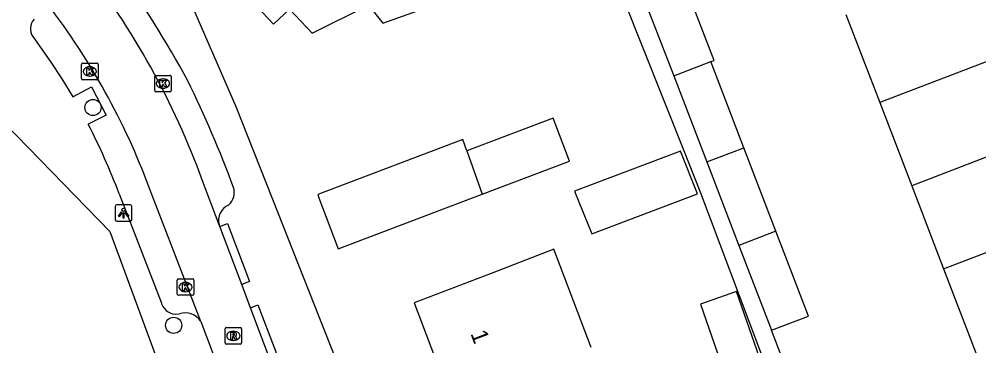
# Model space of a CAD drawing. Extents: x 159961 to 160856, y 382704 to 383353.
# Drawn here: x 160398.7 to 160456.8, y 383072.7 to 383092.5 of the extents above; entities that cross this region are included whole.
import ezdxf

# ---------------------------------------------------------------- set-up
doc = ezdxf.new("R2010")
doc.units = 0
for name, color, linetype in [('IMGEO_Boom', 7, 'Continuous'), ('IMGEO_Kolk', 7, 'Continuous'), ('IMGEO_Lichtpunt', 7, 'Continuous'), ('IMGEO_Pand', 7, 'Continuous'), ('IMGEO_Pand_nummerreeks', 7, 'Continuous'), ('IMGEO_Rijbaan_lokaal_open', 7, 'Continuous'), ('IMGEO_Rioolput', 7, 'Continuous'), ('IMGEO_Voetpad_open', 7, 'Continuous')]:
    doc.layers.add(name, color=color, linetype=linetype)

msp = doc.modelspace()

# ---------------------------------------------------------------- linework, layer by layer
at = {"layer": 'IMGEO_Boom'}
for centre in [(160403.209, 383087.15), (160408.089, 383073.963)]:
    msp.add_circle(centre, 0.489, dxfattribs=at)
at = {"layer": 'IMGEO_Kolk'}
for p, q in [((160402.513, 383088.911), (160402.513, 383089.763)), ((160402.588, 383089.837), (160403.44, 383089.837)), ((160403.514, 383089.763), (160403.514, 383088.911)), ((160403.001, 383089.617), (160403.026, 383089.617)), ((160403.44, 383088.837), (160402.588, 383088.837)), ((160403.024, 383089.057), (160402.999, 383089.057)), ((160406.94, 383088.175), (160406.94, 383089.027)), ((160407.015, 383089.101), (160407.867, 383089.101)), ((160407.428, 383088.881), (160407.453, 383088.881)), ((160407.941, 383089.027), (160407.941, 383088.175)), ((160407.867, 383088.101), (160407.015, 383088.101)), ((160407.451, 383088.321), (160407.426, 383088.321)), ((160408.301, 383075.854), (160408.301, 383076.706)), ((160408.376, 383076.78), (160409.228, 383076.78)), ((160408.789, 383076.56), (160408.814, 383076.56)), ((160409.302, 383076.706), (160409.302, 383075.854)), ((160409.228, 383075.78), (160408.376, 383075.78)), ((160408.812, 383076), (160408.787, 383076))]:
    msp.add_line(p, q, dxfattribs=at)
for points in [[(160402.513, 383088.911), (160402.513, 383089.763)], [(160402.588, 383089.837), (160403.44, 383089.837)], [(160403.514, 383089.763), (160403.514, 383088.911)], [(160402.834, 383089.537), (160402.957, 383089.537), (160402.957, 383089.386), (160403.087, 383089.537), (160403.251, 383089.537), (160403.105, 383089.386), (160403.258, 383089.137), (160403.106, 383089.137), (160403.021, 383089.301), (160402.957, 383089.234), (160402.957, 383089.137), (160402.834, 383089.137), (160402.834, 383089.537)], [(160403.44, 383088.837), (160402.588, 383088.837)], [(160406.94, 383088.175), (160406.94, 383089.027)], [(160407.015, 383089.101), (160407.867, 383089.101)], [(160407.261, 383088.801), (160407.384, 383088.801), (160407.384, 383088.65), (160407.514, 383088.801), (160407.678, 383088.801), (160407.532, 383088.65), (160407.685, 383088.401), (160407.533, 383088.401), (160407.448, 383088.565), (160407.384, 383088.498), (160407.384, 383088.401), (160407.261, 383088.401), (160407.261, 383088.801)], [(160407.941, 383089.027), (160407.941, 383088.175)], [(160407.867, 383088.101), (160407.015, 383088.101)], [(160408.301, 383075.854), (160408.301, 383076.706)], [(160408.376, 383076.78), (160409.228, 383076.78)], [(160408.622, 383076.48), (160408.745, 383076.48), (160408.745, 383076.329), (160408.875, 383076.48), (160409.039, 383076.48), (160408.893, 383076.329), (160409.046, 383076.08), (160408.894, 383076.08), (160408.809, 383076.244), (160408.745, 383076.177), (160408.745, 383076.08), (160408.622, 383076.08), (160408.622, 383076.48)], [(160409.302, 383076.706), (160409.302, 383075.854)], [(160409.228, 383075.78), (160408.376, 383075.78)]]:
    msp.add_lwpolyline(points, dxfattribs=at)
for centre, start, end in [((160402.59, 383089.761), 91.55205, 178.44795), ((160402.59, 383089.761), 91.55205, 178.44795), ((160403.438, 383089.761), 1.55205, 88.44795), ((160403.438, 383089.761), 1.55205, 88.44795), ((160402.59, 383088.913), 181.55205, 268.44795), ((160402.59, 383088.913), 181.55205, 268.44795), ((160403.438, 383088.913), 271.55205, 358.44795), ((160403.438, 383088.913), 271.55205, 358.44795), ((160407.017, 383089.025), 91.55205, 178.44795), ((160407.017, 383089.025), 91.55205, 178.44795), ((160407.865, 383089.025), 1.55205, 88.44795), ((160407.865, 383089.025), 1.55205, 88.44795), ((160407.017, 383088.177), 181.55205, 268.44795), ((160407.017, 383088.177), 181.55205, 268.44795), ((160407.865, 383088.177), 271.55205, 358.44795), ((160407.865, 383088.177), 271.55205, 358.44795), ((160408.378, 383076.704), 91.55205, 178.44795), ((160408.378, 383076.704), 91.55205, 178.44795), ((160409.226, 383076.704), 1.55205, 88.44795), ((160409.226, 383076.704), 1.55205, 88.44795), ((160408.378, 383075.856), 181.55205, 268.44795), ((160408.378, 383075.856), 181.55205, 268.44795), ((160409.226, 383075.856), 271.55205, 358.44795), ((160409.226, 383075.856), 271.55205, 358.44795)]:
    msp.add_arc(centre, 0.0765, start, end, dxfattribs=at)
for centre, major_axis, ratio, start_param, end_param in [((160403, 383089.337), (-0.387, 0.002), 0.722429, 4.712389, 7.853982), ((160403.025, 383089.337), (-0.39, 0.002), 0.717154, 1.570796, 4.712389), ((160407.427, 383088.601), (-0.387, 0.002), 0.722429, 4.712389, 7.853982), ((160407.452, 383088.601), (-0.39, 0.002), 0.717154, 1.570796, 4.712389), ((160408.788, 383076.28), (-0.387, 0.002), 0.722429, 4.712389, 7.853982), ((160408.813, 383076.28), (-0.39, 0.002), 0.717154, 1.570796, 4.712389)]:
    msp.add_ellipse(centre, major_axis=major_axis, ratio=ratio, start_param=start_param, end_param=end_param, dxfattribs=at)
at = {"layer": 'IMGEO_Lichtpunt'}
for p, q in [((160404.557, 383081.165), (160404.557, 383080.358)), ((160404.557, 383081.165), (160404.557, 383080.358)), ((160405.459, 383081.26), (160404.651, 383081.26)), ((160405.459, 383081.26), (160404.651, 383081.26)), ((160405.553, 383080.358), (160405.553, 383081.165)), ((160405.553, 383080.358), (160405.553, 383081.165)), ((160404.651, 383080.264), (160405.459, 383080.264)), ((160404.651, 383080.264), (160405.459, 383080.264))]:
    msp.add_line(p, q, dxfattribs=at)
for points in [[(160404.931, 383080.829), (160404.97, 383080.801), (160404.782, 383080.539), (160404.744, 383080.566), (160404.931, 383080.829)], [(160405.033, 383080.781), (160405.08, 383080.781), (160405.08, 383080.459), (160405.033, 383080.459), (160405.033, 383080.781)], [(160405.143, 383080.801), (160405.181, 383080.828), (160405.368, 383080.566), (160405.329, 383080.538), (160405.143, 383080.801)]]:
    msp.add_lwpolyline(points, dxfattribs=at)
msp.add_circle((160405.056, 383080.963), 0.0994, dxfattribs=at)
for centre, start, end in [((160404.651, 383081.165), 90, 180), ((160404.651, 383081.165), 90, 180), ((160405.459, 383081.165), 0, 90), ((160405.459, 383081.165), 0, 90), ((160404.651, 383080.358), 180, 270), ((160404.651, 383080.358), 180, 270), ((160405.459, 383080.358), 270, 0), ((160405.459, 383080.358), 270, 360)]:
    msp.add_arc(centre, 0.0946, start, end, dxfattribs=at)
at = {"layer": 'IMGEO_Pand'}
for points in [[(160414.649, 383103.168), (160409.479, 383098.316), (160411.655, 383095.998), (160411.077, 383095.456), (160414.136, 383092.196), (160415.099, 383093.1), (160416.461, 383091.649), (160419.873, 383093.345), (160420.737, 383092.269), (160422.841, 383093.012), (160422.27, 383094.628), (160422.461, 383094.808)], [(160440.594, 383089.935), (160440.786, 383090.009), (160438.829, 383095.091), (160436.385, 383094.185)], [(160436.385, 383094.185), (160438.356, 383089.077)], [(160448.772, 383092.79), (160450.819, 383087.447)], [(160460.412, 383091.133), (160450.819, 383087.447)], [(160438.356, 383089.077), (160438.888, 383089.281), (160440.594, 383089.935)], [(160442.593, 383084.717), (160440.594, 383089.935)], [(160438.356, 383089.077), (160440.355, 383083.859)], [(160450.819, 383087.447), (160452.747, 383082.416)], [(160426.766, 383081.902), (160432.041, 383083.901), (160431.055, 383086.501), (160425.839, 383084.525)], [(160462.339, 383086.103), (160452.747, 383082.416)], [(160425.839, 383084.525), (160425.594, 383085.219), (160416.804, 383081.889), (160416.879, 383081.692), (160418.051, 383078.6), (160426.766, 383081.902)], [(160425.839, 383084.525), (160426.766, 383081.902)], [(160432.354, 383082.089), (160433.387, 383079.497), (160439.789, 383081.921), (160438.755, 383084.513), (160432.354, 383082.089)], [(160440.355, 383083.859), (160442.593, 383084.717)], [(160444.532, 383079.658), (160442.593, 383084.717)], [(160440.355, 383083.859), (160442.294, 383078.801)], [(160452.747, 383082.416), (160454.677, 383077.379)], [(160454.677, 383077.379), (160464.27, 383081.065)], [(160444.532, 383079.658), (160442.294, 383078.801)], [(160444.262, 383073.665), (160446.5, 383074.522), (160444.532, 383079.658)], [(160442.294, 383078.801), (160444.262, 383073.665)], [(160433.344, 383072.618), (160431.088, 383078.572), (160427.311, 383077.102), (160422.635, 383075.33), (160424.878, 383069.41)], [(160454.677, 383077.379), (160456.628, 383072.287)], [(160439.969, 383075.245), (160440.996, 383072.284), (160441.355, 383071.247), (160443.542, 383072.006), (160442.156, 383076.003), (160439.969, 383075.245)]]:
    msp.add_lwpolyline(points, dxfattribs=at)
at = {"layer": 'IMGEO_Rijbaan_lokaal_open'}
for points in [[(160409.728, 383074.203), (160406.467, 383082.681)], [(160410.843, 383080.057), (160409.838, 383082.722)], [(160410.882, 383079.95), (160410.843, 383080.057)], [(160412.207, 383076.443), (160410.882, 383079.95)], [(160412.742, 383075.024), (160412.207, 383076.443)], [(160414.077, 383071.485), (160412.742, 383075.024)], [(160409.728, 383074.203), (160410.485, 383072.21)]]:
    msp.add_lwpolyline(points, dxfattribs=at)
for centre, radius, start, end in [((160364.13, 383066.003), 48.67, 20.09171, 37.87621), ((160366.661, 383067.435), 42.626, 20.95735, 38.05807)]:
    msp.add_arc(centre, radius, start, end, dxfattribs=at)
at = {"layer": 'IMGEO_Rioolput'}
for p, q in [((160411.201, 383072.898), (160411.201, 383073.75)), ((160411.276, 383073.824), (160412.128, 383073.824)), ((160411.689, 383073.604), (160411.714, 383073.604)), ((160412.202, 383073.75), (160412.202, 383072.898)), ((160411.712, 383073.044), (160411.687, 383073.044)), ((160412.128, 383072.824), (160411.276, 383072.824))]:
    msp.add_line(p, q, dxfattribs=at)
for points in [[(160411.201, 383072.898), (160411.201, 383073.75)], [(160411.276, 383073.824), (160412.128, 383073.824)], [(160411.79, 383073.522), (160411.538, 383073.524), (160411.538, 383073.124)], [(160411.716, 383073.443), (160411.662, 383073.443), (160411.662, 383073.362)], [(160412.202, 383073.75), (160412.202, 383072.898)], [(160411.538, 383073.124), (160411.662, 383073.124), (160411.662, 383073.286), (160411.673, 383073.286)], [(160411.662, 383073.362), (160411.714, 383073.362)], [(160411.72, 383073.257), (160411.791, 383073.124), (160411.931, 383073.124), (160411.866, 383073.25)], [(160412.128, 383072.824), (160411.276, 383072.824)]]:
    msp.add_lwpolyline(points, dxfattribs=at)
for centre, radius, start, end in [((160411.278, 383073.748), 0.0765, 91.55205, 178.44795), ((160411.278, 383073.748), 0.0765, 91.55205, 178.44795), ((160411.722, 383073.347), 0.0964, 77.00612, 93.18647), ((160411.736, 383073.404), 0.0378, 276.66336, 79.67722), ((160411.789, 383073.412), 0.109, 350.36119, 89.41601), ((160412.126, 383073.748), 0.0765, 1.55205, 88.44795), ((160412.126, 383073.748), 0.0765, 1.55205, 88.44795), ((160411.278, 383072.9), 0.0765, 181.55205, 268.44795), ((160411.278, 383072.9), 0.0765, 181.55205, 268.44795), ((160411.672, 383073.233), 0.0533, 26.02933, 88.69889), ((160411.698, 383073.551), 0.19, 274.7715, 282.96867), ((160411.787, 383073.412), 0.112, 277.58423, 350.98172), ((160411.771, 383073.197), 0.108, 29.51342, 73.79051), ((160412.126, 383072.9), 0.0765, 271.55205, 358.44795), ((160412.126, 383072.9), 0.0765, 271.55205, 358.44795)]:
    msp.add_arc(centre, radius, start, end, dxfattribs=at)
for centre, major_axis, ratio, start_param, end_param in [((160411.688, 383073.324), (-0.387, 0.002), 0.722429, 4.712389, 7.853982), ((160411.713, 383073.324), (-0.39, 0.002), 0.717154, 1.570796, 4.712389)]:
    msp.add_ellipse(centre, major_axis=major_axis, ratio=ratio, start_param=start_param, end_param=end_param, dxfattribs=at)
at = {"layer": 'IMGEO_Voetpad_open'}
for points in [[(160431.776, 383035.564), (160419.63, 383067.53), (160415.599, 383077.746), (160414.428, 383080.713), (160411.87, 383087.197), (160407.676, 383096.869), (160407.237, 383099.321)], [(160436.385, 383094.185), (160435.282, 383093.776), (160438.937, 383084.582), (160439.971, 383081.99), (160454.246, 383044.035), (160449.073, 383042.09)], [(160399.568, 383091.447), (160400.66, 383089.894), (160401.325, 383088.884), (160401.994, 383087.8), (160403.124, 383088.404), (160404.012, 383086.696), (160402.921, 383086.147)], [(160397.167, 383086.9), (160404.22, 383079.65), (160409.328, 383065.794)], [(160404.796, 383081.932), (160407.326, 383075.373)], [(160410.882, 383079.95), (160411.347, 383080.126), (160412.681, 383076.623), (160412.207, 383076.443)], [(160412.742, 383075.024), (160413.183, 383075.194), (160414.543, 383071.664), (160414.077, 383071.485)], [(160408.175, 383074.64), (160408.432, 383074.655)], [(160444.95, 383071.869), (160444.262, 383073.665)]]:
    msp.add_lwpolyline(points, dxfattribs=at)
for centre, radius, start, end in [((160351.786, 383057.856), 64.981, 28.41067, 35.52326), ((160400.255, 383091.929), 0.839, 136.94346, 215.03198), ((160345.033, 383057.554), 71.125, 20.36991, 26.03584), ((160361.301, 383065.108), 46.636, 21.14638, 26.81643), ((160410.744, 383082.006), 1.014, 311.50366, 17.50367), ((160411.809, 383080.325), 1.003, 113.088, 195.4892), ((160408.253, 383075.588), 0.951, 193.06343, 265.32397), ((160408.789, 383073.594), 1.12, 32.97178, 108.5742)]:
    msp.add_arc(centre, radius, start, end, dxfattribs=at)

# ---------------------------------------------------------------- texts
at = {"layer": 'IMGEO_Pand_nummerreeks'}
msp.add_text('1', height=1, rotation=290.75179, dxfattribs=at).set_placement((160426.038, 383073.462))

doc.saveas('drawing.dxf')
